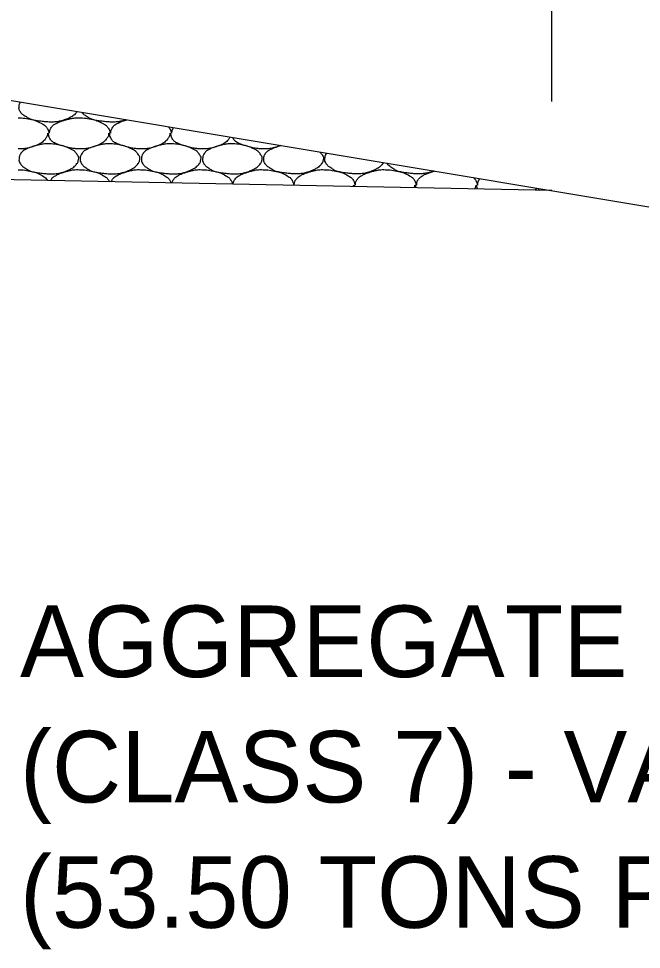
# Model space of a CAD drawing. Extents: x -900 to 15312, y 1857 to 2945.
# Drawn here: x 4238 to 4290.1, y 2382.9 to 2460.9 of the extents above; entities that cross this region are included whole.
import ezdxf

# ---------------------------------------------------------------- set-up
doc = ezdxf.new("R2010")
doc.units = 0
doc.layers.add('R_Annotation', color=7, linetype='Continuous')
doc.layers.add('R_Dimension', color=7, linetype='Continuous')

msp = doc.modelspace()

# ---------------------------------------------------------------- linework, layer by layer
at = {"layer": 'R_Annotation'}
for p, q in [((4214.164, 2457.891), (4374.164, 2431.224)), ((4282.587, 2446.487), (4064.164, 2450.856))]:
    msp.add_line(p, q, dxfattribs=at)
for points in [[(4242.855, 2453.109), (4242.817, 2453.05), (4242.774, 2452.992), (4242.63, 2452.832), (4242.538, 2452.761), (4242.222, 2452.582), (4242.024, 2452.486), (4241.52, 2452.327), (4241.236, 2452.255), (4240.797, 2452.227), (4240.43, 2452.237), (4240.064, 2452.272), (4239.602, 2452.323), (4239.363, 2452.361), (4238.928, 2452.462), (4238.759, 2452.567), (4238.385, 2452.801), (4238.224, 2452.922), (4238.012, 2453.247), (4237.997, 2453.365), (4238.012, 2453.618), (4238.039, 2453.761), (4238.124, 2453.898)], [(4246.953, 2452.426), (4246.944, 2452.423), (4246.65, 2452.329), (4246.356, 2452.255), (4245.917, 2452.227), (4245.55, 2452.237), (4245.184, 2452.272), (4244.722, 2452.323), (4244.483, 2452.361), (4244.048, 2452.462), (4243.879, 2452.567), (4243.537, 2452.781), (4243.397, 2452.883), (4243.274, 2453.039)], [(4237.944, 2452.577), (4237.964, 2452.575), (4237.984, 2452.578), (4238.004, 2452.577)], [(4238.004, 2452.577), (4238.297, 2452.581), (4238.591, 2452.536), (4239.242, 2452.403), (4239.572, 2452.295), (4240.125, 2451.998), (4240.302, 2451.843), (4240.476, 2451.519), (4240.496, 2451.42), (4240.504, 2451.31), (4240.505, 2451.303), (4240.504, 2451.297)], [(4240.564, 2451.297), (4240.564, 2451.303), (4240.566, 2451.479), (4240.615, 2451.647), (4240.834, 2451.948), (4240.97, 2452.036), (4241.256, 2452.185), (4241.385, 2452.25), (4241.723, 2452.364), (4241.921, 2452.424), (4242.25, 2452.509), (4242.558, 2452.581), (4242.878, 2452.593), (4243.064, 2452.577)], [(4243.064, 2452.577), (4243.084, 2452.575), (4243.104, 2452.578), (4243.124, 2452.577)], [(4243.124, 2452.577), (4243.417, 2452.581), (4243.711, 2452.536), (4244.362, 2452.403), (4244.692, 2452.295), (4245.245, 2451.998), (4245.422, 2451.843), (4245.596, 2451.519), (4245.616, 2451.42), (4245.624, 2451.31), (4245.625, 2451.303), (4245.624, 2451.297)], [(4245.684, 2451.297), (4245.684, 2451.303), (4245.686, 2451.479), (4245.735, 2451.647), (4245.954, 2451.948), (4246.09, 2452.036), (4246.376, 2452.185), (4246.505, 2452.25), (4246.769, 2452.339), (4246.894, 2452.378), (4247.02, 2452.415)], [(4240.384, 2451.297), (4240.384, 2451.277), (4240.389, 2451.051), (4240.248, 2450.858), (4240.013, 2450.595), (4239.918, 2450.521), (4239.602, 2450.342), (4239.404, 2450.246), (4238.9, 2450.087), (4238.617, 2450.008), (4238.197, 2449.992), (4238.07, 2449.991), (4237.944, 2449.997)], [(4243.064, 2449.997), (4243.037, 2449.997), (4242.79, 2449.994), (4242.543, 2450.017), (4242.09, 2450.099), (4241.867, 2450.17), (4241.444, 2450.292), (4241.254, 2450.355), (4240.852, 2450.528), (4240.676, 2450.681), (4240.506, 2451.007), (4240.484, 2451.12), (4240.484, 2451.257), (4240.484, 2451.277), (4240.484, 2451.297)], [(4245.504, 2451.297), (4245.504, 2451.277), (4245.509, 2451.051), (4245.368, 2450.858), (4245.133, 2450.595), (4245.038, 2450.521), (4244.722, 2450.342), (4244.524, 2450.246), (4244.02, 2450.087), (4243.737, 2450.008), (4243.317, 2449.992), (4243.19, 2449.991), (4243.064, 2449.997)], [(4248.184, 2449.997), (4248.157, 2449.997), (4247.91, 2449.994), (4247.663, 2450.017), (4247.21, 2450.099), (4246.987, 2450.17), (4246.564, 2450.292), (4246.374, 2450.355), (4245.972, 2450.528), (4245.796, 2450.681), (4245.626, 2451.007), (4245.604, 2451.12), (4245.604, 2451.257), (4245.604, 2451.277), (4245.604, 2451.297)], [(4250.624, 2451.297), (4250.624, 2451.277), (4250.629, 2451.051), (4250.488, 2450.858), (4250.253, 2450.595), (4250.158, 2450.521), (4249.842, 2450.342), (4249.644, 2450.246), (4249.14, 2450.087), (4248.857, 2450.008), (4248.437, 2449.992), (4248.31, 2449.991), (4248.184, 2449.997)], [(4250.514, 2451.833), (4250.57, 2451.769), (4250.621, 2451.697), (4250.716, 2451.519), (4250.736, 2451.42), (4250.744, 2451.31), (4250.745, 2451.303), (4250.744, 2451.297)], [(4253.304, 2449.997), (4253.277, 2449.997), (4253.03, 2449.994), (4252.783, 2450.017), (4252.33, 2450.099), (4252.107, 2450.17), (4251.684, 2450.292), (4251.494, 2450.355), (4251.092, 2450.528), (4250.916, 2450.681), (4250.746, 2451.007), (4250.724, 2451.12), (4250.724, 2451.257), (4250.724, 2451.277), (4250.724, 2451.297)], [(4250.804, 2451.297), (4250.804, 2451.303), (4250.806, 2451.466), (4250.848, 2451.622), (4250.94, 2451.762)], [(4240.504, 2450.397), (4240.797, 2450.401), (4241.091, 2450.356), (4241.742, 2450.223), (4242.072, 2450.115), (4242.625, 2449.818), (4242.777, 2449.657), (4242.987, 2449.342), (4243.021, 2449.232), (4242.97, 2448.949), (4242.872, 2448.762), (4242.63, 2448.492), (4242.538, 2448.421), (4242.222, 2448.242), (4242.024, 2448.146), (4241.52, 2447.987), (4241.236, 2447.915), (4240.797, 2447.887), (4240.43, 2447.897), (4240.064, 2447.932), (4239.602, 2447.983), (4239.363, 2448.021), (4238.928, 2448.122), (4238.759, 2448.227), (4238.385, 2448.461), (4238.224, 2448.582), (4238.012, 2448.907), (4237.997, 2449.025), (4238.013, 2449.299), (4238.047, 2449.462), (4238.282, 2449.773), (4238.41, 2449.856), (4238.696, 2450.005), (4238.825, 2450.07), (4239.163, 2450.184), (4239.361, 2450.244), (4239.69, 2450.329), (4239.998, 2450.401), (4240.318, 2450.413), (4240.504, 2450.397)], [(4245.624, 2450.397), (4245.917, 2450.401), (4246.211, 2450.356), (4246.862, 2450.223), (4247.192, 2450.115), (4247.745, 2449.818), (4247.897, 2449.657), (4248.107, 2449.342), (4248.141, 2449.232), (4248.09, 2448.949), (4247.992, 2448.762), (4247.75, 2448.492), (4247.658, 2448.421), (4247.342, 2448.242), (4247.144, 2448.146), (4246.64, 2447.987), (4246.356, 2447.915), (4245.917, 2447.887), (4245.55, 2447.897), (4245.184, 2447.932), (4244.722, 2447.983), (4244.483, 2448.021), (4244.048, 2448.122), (4243.879, 2448.227), (4243.505, 2448.461), (4243.344, 2448.582), (4243.132, 2448.907), (4243.117, 2449.025), (4243.133, 2449.299), (4243.167, 2449.462), (4243.402, 2449.773), (4243.53, 2449.856), (4243.816, 2450.005), (4243.945, 2450.07), (4244.283, 2450.184), (4244.481, 2450.244), (4244.81, 2450.329), (4245.118, 2450.401), (4245.438, 2450.413), (4245.624, 2450.397)], [(4250.744, 2450.397), (4251.037, 2450.401), (4251.331, 2450.356), (4251.982, 2450.223), (4252.312, 2450.115), (4252.865, 2449.818), (4253.017, 2449.657), (4253.227, 2449.342), (4253.261, 2449.232), (4253.21, 2448.949), (4253.112, 2448.762), (4252.87, 2448.492), (4252.778, 2448.421), (4252.462, 2448.242), (4252.264, 2448.146), (4251.76, 2447.987), (4251.476, 2447.915), (4251.037, 2447.887), (4250.67, 2447.897), (4250.304, 2447.932), (4249.842, 2447.983), (4249.603, 2448.021), (4249.168, 2448.122), (4248.999, 2448.227), (4248.625, 2448.461), (4248.464, 2448.582), (4248.252, 2448.907), (4248.237, 2449.025), (4248.253, 2449.299), (4248.287, 2449.462), (4248.522, 2449.773), (4248.65, 2449.856), (4248.936, 2450.005), (4249.065, 2450.07), (4249.403, 2450.184), (4249.601, 2450.244), (4249.93, 2450.329), (4250.238, 2450.401), (4250.558, 2450.413), (4250.744, 2450.397)], [(4255.668, 2450.974), (4255.615, 2450.876), (4255.542, 2450.784), (4255.373, 2450.595), (4255.278, 2450.521), (4254.962, 2450.342), (4254.764, 2450.246), (4254.26, 2450.087), (4253.977, 2450.008), (4253.557, 2449.992), (4253.43, 2449.991), (4253.304, 2449.997)], [(4255.864, 2450.397), (4256.157, 2450.401), (4256.451, 2450.356), (4257.102, 2450.223), (4257.432, 2450.115), (4257.985, 2449.818), (4258.137, 2449.657), (4258.347, 2449.342), (4258.381, 2449.232), (4258.33, 2448.949), (4258.232, 2448.762), (4257.99, 2448.492), (4257.898, 2448.421), (4257.582, 2448.242), (4257.384, 2448.146), (4256.88, 2447.987), (4256.596, 2447.915), (4256.157, 2447.887), (4255.79, 2447.897), (4255.424, 2447.932), (4254.962, 2447.983), (4254.723, 2448.021), (4254.288, 2448.122), (4254.119, 2448.227), (4253.745, 2448.461), (4253.584, 2448.582), (4253.372, 2448.907), (4253.357, 2449.025), (4253.373, 2449.299), (4253.407, 2449.462), (4253.642, 2449.773), (4253.77, 2449.856), (4254.056, 2450.005), (4254.185, 2450.07), (4254.523, 2450.184), (4254.721, 2450.244), (4255.05, 2450.329), (4255.358, 2450.401), (4255.678, 2450.413), (4255.864, 2450.397)], [(4258.424, 2449.997), (4258.397, 2449.997), (4258.15, 2449.994), (4257.903, 2450.017), (4257.45, 2450.099), (4257.227, 2450.17), (4256.804, 2450.292), (4256.614, 2450.355), (4256.212, 2450.528), (4256.036, 2450.681), (4255.917, 2450.909), (4255.911, 2450.922), (4255.906, 2450.934)], [(4259.907, 2450.267), (4259.828, 2450.233), (4259.464, 2450.11), (4259.097, 2450.008), (4258.677, 2449.992), (4258.55, 2449.991), (4258.424, 2449.997)], [(4263.174, 2449.723), (4263.257, 2449.641), (4263.331, 2449.546), (4263.467, 2449.342), (4263.501, 2449.232), (4263.45, 2448.949), (4263.352, 2448.762), (4263.11, 2448.492), (4263.018, 2448.421), (4262.702, 2448.242), (4262.504, 2448.146), (4262, 2447.987), (4261.716, 2447.915), (4261.277, 2447.887), (4260.91, 2447.897), (4260.544, 2447.932), (4260.082, 2447.983), (4259.843, 2448.021), (4259.408, 2448.122), (4259.239, 2448.227), (4258.865, 2448.461), (4258.704, 2448.582), (4258.492, 2448.907), (4258.477, 2449.025), (4258.493, 2449.299), (4258.527, 2449.462), (4258.762, 2449.773), (4258.89, 2449.856), (4259.176, 2450.005), (4259.305, 2450.07), (4259.603, 2450.17), (4259.762, 2450.22), (4259.924, 2450.264)], [(4268.495, 2448.836), (4268.449, 2448.753), (4268.392, 2448.673), (4268.23, 2448.492), (4268.138, 2448.421), (4267.822, 2448.242), (4267.624, 2448.146), (4267.12, 2447.987), (4266.836, 2447.915), (4266.397, 2447.887), (4266.03, 2447.897), (4265.664, 2447.932), (4265.202, 2447.983), (4264.963, 2448.021), (4264.528, 2448.122), (4264.359, 2448.227), (4263.985, 2448.461), (4263.824, 2448.582), (4263.612, 2448.907), (4263.597, 2449.025), (4263.613, 2449.299), (4263.647, 2449.462), (4263.766, 2449.619), (4263.767, 2449.621), (4263.769, 2449.623)], [(4237.944, 2448.237), (4237.964, 2448.235), (4237.984, 2448.238), (4238.004, 2448.237)], [(4238.004, 2448.237), (4238.297, 2448.241), (4238.591, 2448.196), (4239.242, 2448.063), (4239.572, 2447.955), (4240.107, 2447.668), (4240.273, 2447.528), (4240.393, 2447.331)], [(4240.645, 2447.326), (4240.667, 2447.37), (4240.796, 2447.583), (4240.97, 2447.696), (4241.256, 2447.845), (4241.385, 2447.91), (4241.723, 2448.024), (4241.921, 2448.084), (4242.25, 2448.169), (4242.558, 2448.241), (4242.878, 2448.253), (4243.064, 2448.237)], [(4243.064, 2448.237), (4243.084, 2448.235), (4243.104, 2448.238), (4243.124, 2448.237)], [(4243.124, 2448.237), (4243.417, 2448.241), (4243.711, 2448.196), (4244.362, 2448.063), (4244.692, 2447.955), (4245.245, 2447.658), (4245.422, 2447.503), (4245.553, 2447.26), (4245.561, 2447.244), (4245.568, 2447.228)], [(4245.725, 2447.224), (4245.751, 2447.304), (4245.79, 2447.382), (4245.954, 2447.608), (4246.09, 2447.696), (4246.376, 2447.845), (4246.505, 2447.91), (4246.843, 2448.024), (4247.041, 2448.084), (4247.37, 2448.169), (4247.678, 2448.241), (4247.998, 2448.253), (4248.184, 2448.237)], [(4248.184, 2448.237), (4248.204, 2448.235), (4248.224, 2448.238), (4248.244, 2448.237)], [(4248.244, 2448.237), (4248.537, 2448.241), (4248.831, 2448.196), (4249.482, 2448.063), (4249.812, 2447.955), (4250.365, 2447.658), (4250.542, 2447.503), (4250.691, 2447.226), (4250.709, 2447.176), (4250.722, 2447.124)], [(4250.819, 2447.122), (4250.841, 2447.239), (4250.887, 2447.351), (4251.074, 2447.608), (4251.21, 2447.696), (4251.496, 2447.845), (4251.625, 2447.91), (4251.963, 2448.024), (4252.161, 2448.084), (4252.49, 2448.169), (4252.798, 2448.241), (4253.118, 2448.253), (4253.304, 2448.237)], [(4253.304, 2448.237), (4253.324, 2448.235), (4253.344, 2448.238), (4253.364, 2448.237)], [(4253.364, 2448.237), (4253.657, 2448.241), (4253.951, 2448.196), (4254.602, 2448.063), (4254.932, 2447.955), (4255.485, 2447.658), (4255.662, 2447.503), (4255.829, 2447.193), (4255.849, 2447.109), (4255.86, 2447.022)], [(4255.926, 2447.02), (4255.936, 2447.173), (4255.985, 2447.32), (4256.194, 2447.608), (4256.33, 2447.696), (4256.616, 2447.845), (4256.745, 2447.91), (4257.083, 2448.024), (4257.281, 2448.084), (4257.61, 2448.169), (4257.918, 2448.241), (4258.238, 2448.253), (4258.424, 2448.237)], [(4258.424, 2448.237), (4258.444, 2448.235), (4258.464, 2448.238), (4258.484, 2448.237)], [(4258.484, 2448.237), (4258.777, 2448.241), (4259.071, 2448.196), (4259.722, 2448.063), (4260.052, 2447.955), (4260.605, 2447.658), (4260.782, 2447.503), (4260.956, 2447.179), (4260.976, 2447.08), (4260.984, 2446.97), (4260.985, 2446.963), (4260.984, 2446.957)], [(4261.044, 2446.957), (4261.044, 2446.963), (4261.046, 2447.139), (4261.095, 2447.307), (4261.314, 2447.608), (4261.45, 2447.696), (4261.736, 2447.845), (4261.865, 2447.91), (4262.203, 2448.024), (4262.401, 2448.084), (4262.73, 2448.169), (4263.038, 2448.241), (4263.358, 2448.253), (4263.544, 2448.237)], [(4263.544, 2448.237), (4263.564, 2448.235), (4263.584, 2448.238), (4263.604, 2448.237)], [(4263.604, 2448.237), (4263.897, 2448.241), (4264.191, 2448.196), (4264.842, 2448.063), (4265.172, 2447.955), (4265.725, 2447.658), (4265.902, 2447.503), (4266.076, 2447.179), (4266.096, 2447.08), (4266.104, 2446.97), (4266.105, 2446.963), (4266.104, 2446.957)], [(4266.164, 2446.957), (4266.164, 2446.963), (4266.166, 2447.139), (4266.215, 2447.307), (4266.434, 2447.608), (4266.57, 2447.696), (4266.856, 2447.845), (4266.985, 2447.91), (4267.323, 2448.024), (4267.521, 2448.084), (4267.85, 2448.169), (4268.158, 2448.241), (4268.478, 2448.253), (4268.664, 2448.237)], [(4268.664, 2448.237), (4268.684, 2448.235), (4268.704, 2448.238), (4268.724, 2448.237)], [(4268.724, 2448.237), (4269.017, 2448.241), (4269.311, 2448.196), (4269.962, 2448.063), (4270.292, 2447.955), (4270.845, 2447.658), (4271.022, 2447.503), (4271.196, 2447.179), (4271.216, 2447.08), (4271.224, 2446.97), (4271.225, 2446.963), (4271.224, 2446.957)], [(4272.692, 2448.136), (4272.637, 2448.115), (4272.297, 2448.001), (4271.956, 2447.915), (4271.517, 2447.887), (4271.15, 2447.897), (4270.784, 2447.932), (4270.322, 2447.983), (4270.083, 2448.021), (4269.648, 2448.122), (4269.479, 2448.227), (4269.11, 2448.458), (4268.951, 2448.577), (4268.813, 2448.783)], [(4271.284, 2446.957), (4271.284, 2446.963), (4271.286, 2447.139), (4271.335, 2447.307), (4271.554, 2447.608), (4271.69, 2447.696), (4271.976, 2447.845), (4272.105, 2447.91), (4272.423, 2448.017), (4272.602, 2448.072), (4272.785, 2448.121)], [(4276.027, 2447.581), (4276.12, 2447.496), (4276.2, 2447.396), (4276.316, 2447.179), (4276.336, 2447.08), (4276.344, 2446.97), (4276.345, 2446.963), (4276.344, 2446.957)], [(4276.404, 2446.957), (4276.404, 2446.963), (4276.406, 2447.139), (4276.455, 2447.307), (4276.572, 2447.467), (4276.579, 2447.477), (4276.587, 2447.487)], [(4260.864, 2446.957), (4260.864, 2446.945), (4260.864, 2446.933), (4260.864, 2446.922)], [(4260.964, 2446.92), (4260.964, 2446.932), (4260.964, 2446.944), (4260.964, 2446.957)], [(4265.984, 2446.957), (4265.984, 2446.937), (4265.985, 2446.89), (4265.98, 2446.845), (4265.975, 2446.819)], [(4266.088, 2446.817), (4266.085, 2446.843), (4266.084, 2446.89), (4266.084, 2446.937), (4266.084, 2446.957)], [(4271.104, 2446.957), (4271.104, 2446.937), (4271.106, 2446.854), (4271.088, 2446.775), (4271.066, 2446.718)], [(4271.225, 2446.714), (4271.21, 2446.774), (4271.204, 2446.855), (4271.204, 2446.937), (4271.204, 2446.957)], [(4276.224, 2446.957), (4276.224, 2446.937), (4276.227, 2446.816), (4276.187, 2446.704), (4276.138, 2446.616)], [(4276.378, 2446.611), (4276.34, 2446.705), (4276.324, 2446.799), (4276.324, 2446.917), (4276.324, 2446.937), (4276.324, 2446.957)], [(4281.3, 2446.702), (4281.273, 2446.637), (4281.236, 2446.575), (4281.193, 2446.515)], [(4281.551, 2446.508), (4281.542, 2446.524), (4281.511, 2446.578), (4281.488, 2446.633), (4281.476, 2446.672)]]:
    msp.add_open_spline(points, degree=3, dxfattribs=at)
at = {"layer": 'R_Dimension'}
msp.add_line((4282.587, 2453.949), (4282.587, 2523.524), dxfattribs=at)

# ---------------------------------------------------------------- texts
at = {"layer": 'R_Annotation'}
for s, p in [('AGGREGATE BASE COURSE', (4238.088, 2405.74)), ("(CLASS 7) - VAR. COMP'D. DEPTH", (4238.088, 2395.24)), ('(53.50 TONS PER STA.)', (4238.088, 2384.74))]:
    msp.add_text(s, height=6, dxfattribs=at).set_placement(p)

doc.saveas('drawing.dxf')
